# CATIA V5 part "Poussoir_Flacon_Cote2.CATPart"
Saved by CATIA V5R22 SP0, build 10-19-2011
Part number: Poussoir_Flacon_Cote
Bounding box of the stored display mesh (mm): x 0 to 5, y -97.5 to 82.5, z -24.5 to 24.5
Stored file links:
  C:\Users\La forge\Desktop\CAO_PER_pick&place_2023A\Sous_Ensemble_Flacon\Verin\Poussoir_Flacon\Poussoir_Flacon_Cote2.CATPart
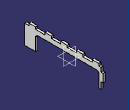
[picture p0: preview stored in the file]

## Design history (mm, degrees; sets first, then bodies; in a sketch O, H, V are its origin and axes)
Body1 (main body)
  Sketch1 on yz-plane, origin (0, 0, 0), H (0, 1, 0), V (0, 0, 1)
    line L1 (82.5, -24.5) -> (72.5, -24.5)
    line L2 (-97.5, -24.5) -> (-97.5, 24.5)
    line L3 (-97.5, 24.5) -> (82.5, 24.5)
    line L4 (82.5, 24.5) -> (82.5, -24.5)
    point P5 (72.5, -24.5)
    line L5 (-72.5, -24.5) -> (-72.5, 4.5)
    line L6 (-67.5, 9.5) -> (67.5, 9.5)
    line L7 (72.5, 4.5) -> (72.5, -24.5)
    point P7 (72.5, 9.5)
    line L8 (-72.5, -24.5) -> (-97.5, -24.5)
    arc A1 centre (-67.5, 4.5) radius 5 from (-72.5, 4.5) to (-67.5, 9.5) cw
    arc A2 centre (67.5, 4.5) radius 5 from (72.5, 4.5) to (67.5, 9.5) ccw
    length L3 = 180
    length L4 = 49
    radius A1 = 5
    distance P7 P5 = 34
    radius A2 = 5
    distance L7 L4 = 10
    distance L2 L5 = 25
    horizontal: L1 H, L3 H, L6 H, L8 H
    vertical: L2 V, L4 V, L5 V, L7 V
    equidistance: L1 L3 O, L7 L5 O
    coincidence: L1 L8, L7 P7, L6 P7
    tangency: A1 L5, A1 L6, A2 L7, A2 L6
  Pad1: profile Sketch1, direction (1, 0, 0), length 5
  Sketch2 on end face of Pad1, origin (5, 0, 0), H (0, 1, 0), V (0, 0, 1)
    point P1 (82.5, -24.5)
    line L1 (82.5, -24.5) -> (77.5, -24.5)
    line L2 (77.5, -24.5) -> (77.5, -9.5)
    line L3 (77.5, -9.5) -> (82.5, -9.5)
    line L4 (82.5, -9.5) -> (82.5, -24.5)
    point P2 (77.5, -24.5)
    point P3 (77.5, -9.5)
    point P4 (82.5, -9.5)
    reference projected line E1 (82.5, -24.5) -> (82.5, 24.5) from edge [face of Pad1 from Sketch1.L4 | end face of Pad1]
    reference projected line E2 (72.5, -24.5) -> (82.5, -24.5) from edge [face of Pad1 from Sketch1.L1 | end face of Pad1]
    point P5 (82.5, 24.5)
    point P6 (77.5, 24.5)
    point P7 (77.5, 9.5)
    point P8 (82.5, 9.5)
    line L5 (82.5, 24.5) -> (77.5, 24.5)
    line L6 (77.5, 24.5) -> (77.5, 9.5)
    line L7 (77.5, 9.5) -> (82.5, 9.5)
    line L8 (82.5, 9.5) -> (82.5, 24.5)
    length L2 = 15
    length L3 = 5
    horizontal: L1 H, L3 H
    vertical: L2 V, L4 V
    coincidence: L4 E1, E2 L1
    symmetry: P1 P5 H, P2 P6 H, P3 P7 H, P4 P8 H, L1 L5 H, L2 L6 H, L3 L7 H, L4 L8 H
  Pocket1: profile Sketch2, direction (-1, 0, 0), length 5
  Sketch3 on end face of Pad1, origin (5, 0, 0), H (0, 1, 0), V (0, 0, 1)
    point P1 (72.5, 19.5)
    line L1 (72.5, 19.5) -> (77.5, 19.5)
    line L2 (77.5, 19.5) -> (77.5, 24.5)
    line L3 (77.5, 24.5) -> (72.5, 24.5)
    line L4 (72.5, 24.5) -> (72.5, 19.5)
    point P2 (77.5, 19.5)
    point P3 (77.5, 24.5)
    point P4 (72.5, 24.5)
    reference projected point E1 (77.5, 24.5) from vertex [face of Pad1 from Sketch1.L3 | face of Pocket1 from Sketch2.L6 | end face of Pad1]
    point P5 (57.5, 19.5)
    line L5 (57.5, 19.5) -> (36.25, 19.5)
    line L6 (36.25, 19.5) -> (36.25, 24.5)
    line L7 (36.25, 24.5) -> (57.5, 24.5)
    line L8 (57.5, 24.5) -> (57.5, 19.5)
    point P6 (36.25, 19.5)
    point P7 (36.25, 24.5)
    point P9 (21.25, 19.5)
    line L9 (21.25, 19.5) -> (0, 19.5)
    line L10 (0, 19.5) -> (0, 24.5)
    line L11 (0, 24.5) -> (21.25, 24.5)
    line L12 (21.25, 24.5) -> (21.25, 19.5)
    point P11 (0, 24.5)
    point P13 (-15, 19.5)
    line L13 (-15, 19.5) -> (-36.25, 19.5)
    line L14 (-36.25, 19.5) -> (-36.25, 24.5)
    line L15 (-36.25, 24.5) -> (-15, 24.5)
    line L16 (-15, 24.5) -> (-15, 19.5)
    point P15 (-36.25, 24.5)
    point P17 (-51.25, 19.5)
    line L17 (-51.25, 19.5) -> (-72.5, 19.5)
    line L18 (-72.5, 19.5) -> (-72.5, 24.5)
    line L19 (-72.5, 24.5) -> (-51.25, 24.5)
    line L20 (-51.25, 24.5) -> (-51.25, 19.5)
    point P18 (-72.5, 19.5)
    point P19 (-72.5, 24.5)
    point P21 (-87.5, 19.5)
    line L21 (-87.5, 19.5) -> (-100, 19.5)
    line L22 (-100, 19.5) -> (-100, 24.5)
    line L23 (-100, 24.5) -> (-87.5, 24.5)
    line L24 (-87.5, 24.5) -> (-87.5, 19.5)
    point P23 (-100, 24.5)
    distance P3 E1 = 0
    distance P1 P2 = 5
    distance P4 P1 = 5
    distance P6 P5 = 21.25
    distance L8 L4 = 15
    distance L6 L12 = 15
    distance L12 L10 = 21.25
    distance L16 L10 = 15
    distance L14 L16 = 21.25
    distance L20 L14 = 15
    distance P18 P17 = 21.25
    distance L18 L24 = 15
    horizontal: L1 H, L3 H, L5 H, L7 H, L9 H, L11 H, L13 H, L15 H, L17 H, L19 H, L21 H, L23 H
    vertical: L2 V, L4 V, L6 V, L8 V, L10 V, L12 V, L14 V, L16 V, L18 V, L20 V, L22 V, L24 V
    coincidence: P5 L1, P7 L3, P9 L1, P11 L3, P13 L1, P15 L3, P17 L1, P19 L3, P21 L1, P23 L3
  Pocket2: profile Sketch3, direction (-1, 0, 0), length 5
